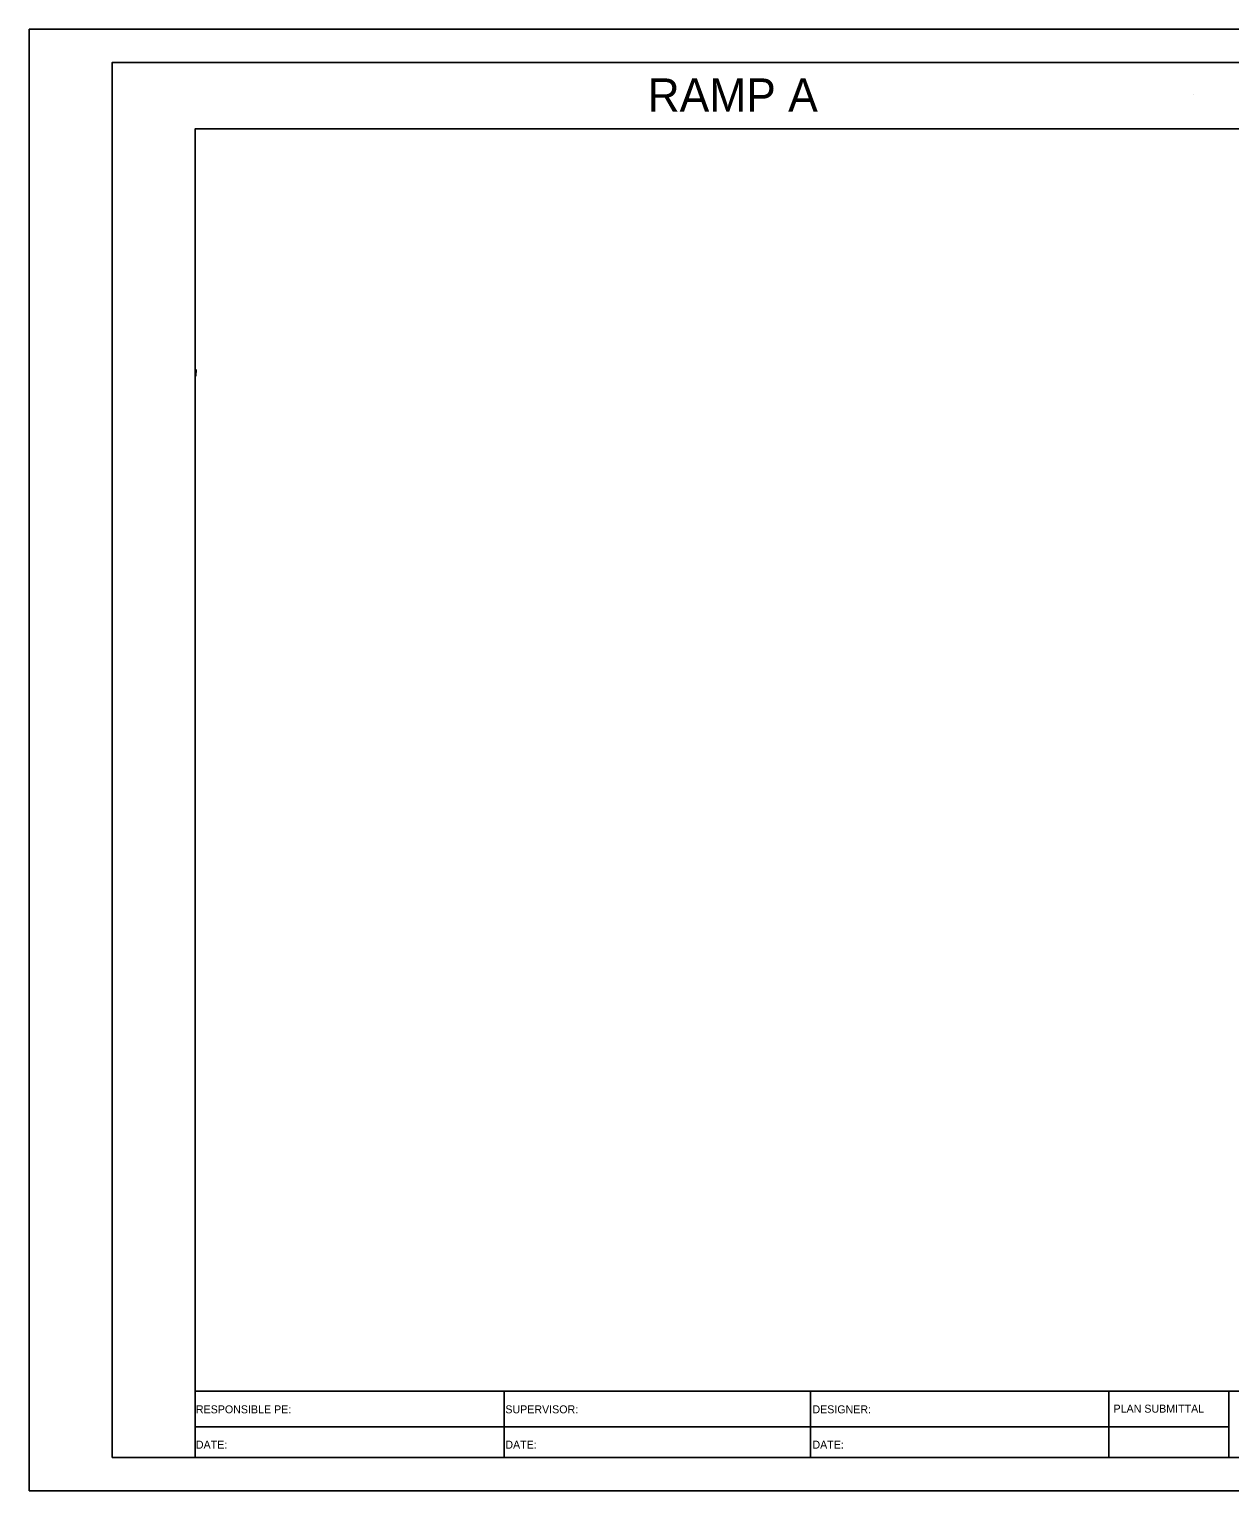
# Model space of a CAD drawing. Extents: x 1797478 to 1804836, y 246529 to 250952.
# Drawn here: x 1802116 to 1802296.8, y 250064.4 to 250284.4 of the extents above; entities that cross this region are included whole.
import ezdxf

# ---------------------------------------------------------------- set-up
doc = ezdxf.new("R2010")
doc.units = 0
for name, color, linetype in [('2', 7, 'Continuous'), ('ANNO-SHT', 7, 'Continuous'), ('ANNO-TXT', 7, 'Continuous'), ('AXIS', 7, 'Continuous'), ('DRAINAGE', 7, 'Continuous'), ('Level 1', 7, 'Continuous'), ('Level 62', 7, 'Continuous'), ('SHT-BDR', 7, 'Continuous'), ('SHT-BNDRY', 7, 'Continuous')]:
    doc.layers.add(name, color=color, linetype=linetype)

# ---------------------------------------------------------------- blocks, each defined once
blk = doc.blocks.new('SC47208')
at = {"layer": 'Level 1'}
blk.add_line((0, 0), (0, 0), dxfattribs=at)

msp = doc.modelspace()

# ---------------------------------------------------------------- linework, layer by layer
at = {"layer": '2'}
msp.add_lwpolyline([(1802141.12, 250233.21), (1802141.1, 250232.21)], dxfattribs=at)
msp.add_lwpolyline([(1802141.12, 250233.21), (1802141.1, 250232.21)], dxfattribs=at)
at = {"layer": 'AXIS'}
msp.add_line((1802141, 250189.42), (1802141, 250189.43), dxfattribs=at)
at = {"layer": 'Level 62'}
msp.add_lwpolyline([(1802116, 250064.42), (1802456, 250064.42), (1802456, 250284.42), (1802116, 250284.42)], close=True, dxfattribs=at)
at = {"layer": 'SHT-BDR'}
msp.add_lwpolyline([(1802141, 250079.43), (1802441, 250079.43), (1802441, 250269.43), (1802141, 250269.43)], close=True, dxfattribs=at)
at = {"layer": 'SHT-BNDRY'}
for p, q in [((1802141, 250069.42), (1802141, 250079.43)), ((1802187.52, 250079.43), (1802187.52, 250069.42)), ((1802233.67, 250069.42), (1802233.67, 250079.43)), ((1802278.59, 250069.42), (1802278.59, 250079.43)), ((1802296.63, 250069.42), (1802296.63, 250079.43)), ((1802141, 250074.03), (1802296.63, 250074.03))]:
    msp.add_line(p, q, dxfattribs=at)
msp.add_lwpolyline([(1802128.5, 250069.42), (1802451, 250069.42), (1802451, 250279.42), (1802128.5, 250279.42)], close=True, dxfattribs=at)

# ---------------------------------------------------------------- block references
at = {"layer": 'DRAINAGE', "xscale": 0.2, "yscale": 0.20000000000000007, "rotation": -116.41666666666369}
msp.add_blockref('SC47208', (1802291.32, 250274.62), dxfattribs=at)
msp.add_blockref('SC47208', (1802291.32, 250274.62), dxfattribs=at)

# ---------------------------------------------------------------- texts
at = {"layer": 'ANNO-SHT'}
msp.add_text('                 RAMP A                 ', height=4.9995, rotation=360, dxfattribs=at).set_placement((1802177.54, 250272.02))
at = {"layer": 'ANNO-TXT'}
for s, p in [('RESPONSIBLE PE:', (1802141.1, 250076.08)), ('SUPERVISOR:', (1802187.7, 250076.08)), ('DESIGNER:', (1802233.94, 250076.08)), ('PLAN SUBMITTAL', (1802279.28, 250076.18)), ('DATE:', (1802141.1, 250070.76)), ('DATE:', (1802187.7, 250070.76)), ('DATE:', (1802233.94, 250070.76))]:
    msp.add_text(s, height=1.2, rotation=360, dxfattribs=at).set_placement(p)

doc.saveas('drawing.dxf')
